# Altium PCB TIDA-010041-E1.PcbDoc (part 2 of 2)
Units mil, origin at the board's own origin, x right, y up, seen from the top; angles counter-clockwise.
Board outline 3937.01 x 2165.35 mil, 2 copper layers (Top Layer, Bottom Layer), stack 62 mil thick; 146 components, 79 nets, 325 pads, 93 vias.
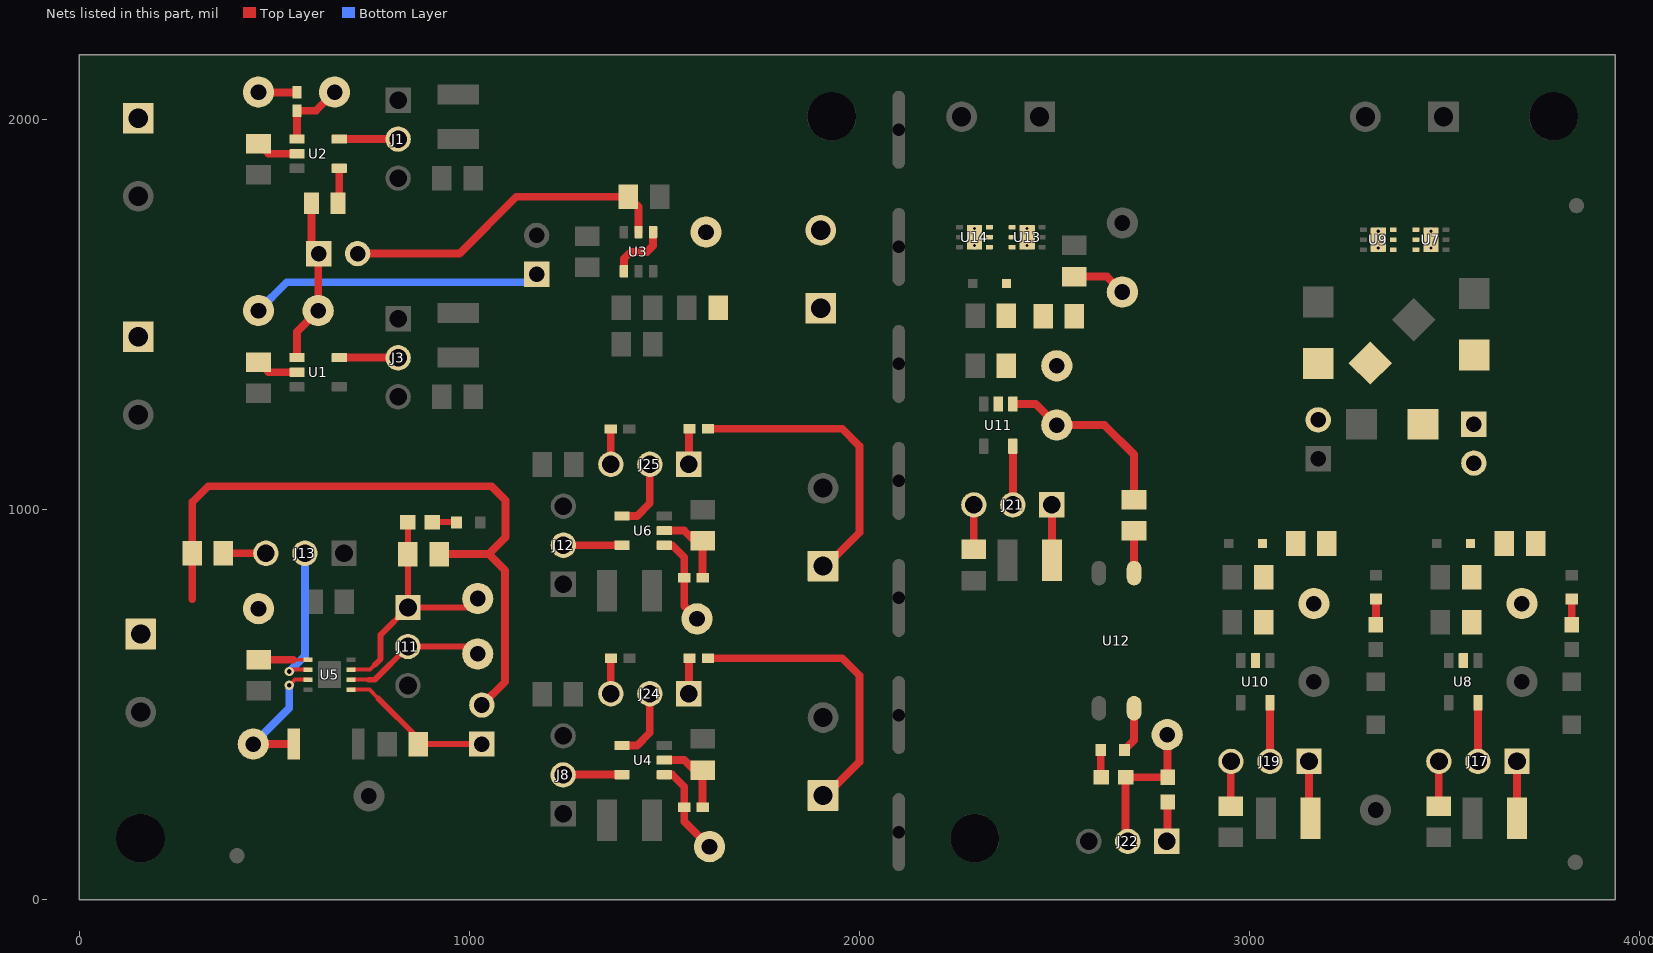
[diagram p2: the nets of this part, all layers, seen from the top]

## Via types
v1: diameter 24, hole 12, Top Layer to Bottom Layer, 81 vias
v2: diameter 19.68, hole 7.87, Top Layer to Bottom Layer, 12 vias

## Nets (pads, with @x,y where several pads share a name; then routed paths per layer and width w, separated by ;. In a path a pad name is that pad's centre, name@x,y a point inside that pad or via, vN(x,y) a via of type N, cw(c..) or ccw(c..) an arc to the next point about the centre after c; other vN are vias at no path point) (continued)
NetC17_1: C17.1 J17.1 | length 145.9
  Top Layer w20: J17.1@3685.4,354.6 3685.4,209.69 C17.1@3686.09,209
NetC18_2: C18.2 D5.1 R7.1 R9.2 TP16.1 U8.2
NetC19_1: C19.1 J17.3 | length 114.8
  Top Layer w20: C19.1@3485,240 3485,354.2 J17.3@3485.4,354.6
NetC20_1: C20.1 J19.1 | length 145.9
  Top Layer w20: J19.1@3152.4,354.6 3152.4,209.69 C20.1@3153.09,209
NetC21_2: C21.2 D8.1 R8.1 R10.2 TP17.1 U10.2
NetC22_1: C22.1 J19.3 | length 114.8
  Top Layer w20: C22.1@2952,240 2952,354.2 J19.3@2952.4,354.6
NetC23_1: C23.1 J21.1 | length 142
  Top Layer w20: C23.1@2493.4,870.1 J21.1@2493.4,1012.1
NetC24_2: C24.2 D10.1 R12.1 R14.2 TP20.1 U11.2
NetC25_1: C25.1 J21.3 | length 114.2
  Top Layer w20: C25.1@2293.4,897.9 J21.3@2293.4,1012.1
NetD2_1: D2.1 D3.1 J16.1
NetD6_2: D6.2 D7.2 J20.2
NetD9_1: D9.1 R17.1 | length 70.4
  Top Layer w20: D9.1@2618.49,384 2618.49,315.02 R17.1@2619.5,314
NetD9_2: D9.2 U12.4 | length 116.9
  Top Layer w20: D9.2@2679.51,384 2704.02,408.51 U12.4@2704.02,490.77
NetD11_1: D11.1 R25.2 | length 62.4
  Top Layer w15: R25.2@905.5,968 966.49,968 D11.1@967.49,967
NetD12_1: D12.1 R26.1 | length 66
  Top Layer w20: R26.1@3826,704.5 D12.1@3826,770.49
NetD13_1: D13.1 R27.1 | length 66
  Top Layer w20: R27.1@3324,704.5 D13.1@3324,770.49
NetJ1_2: J1.2 U2.5 | length 150.9
  Top Layer w20: U2.5@667.13,1949.4 J1.2@818,1949.4
NetJ2_2: J2.2 R2.2 U3.5 | length 855.9
  Top Layer w20: J2.2@714,1656 975,1656 1120.89,1801.89 R2.2@1407.89,1801.89 1433.89,1775.89 U3.5@1433.89,1711.09
NetJ3_2: J3.2 U1.5 | length 150.9
  Top Layer w20: U1.5@667.13,1389.4 J3.2@818,1389.4
NetJ7_1: J7.1 R3.2
NetJ8_2: J8.2 U4.5 | length 150.3
  Top Layer w20: J8.2@1241.49,320.6 U4.5@1391.76,320.6
NetJ11_1: J11.1 R5.2 R25.1 TP8.1 U5.7 | length 655.8
  Top Layer w10: U5.7@697.24,589.59 745.59,589.59 758.5,602.5
  Top Layer w15: 758.5,602.5 773,617 773,679 J11.1@843,749 ; R25.1@842.5,968 843,967.5 R5.2@843,886 J11.1@843,749 ; TP8.1@1022,772 999,749 J11.1@843,749
NetJ11_2: J11.2 TP9.1 U5.6 | length 367.8
  Top Layer w10: U5.6@697.24,564 742,564
  Top Layer w15: 742,564 758,564 J11.2@843,649 1003,649 TP9.1@1022,630
NetJ12_2: J12.2 U6.5 | length 150.3
  Top Layer w20: J12.2@1241.49,908.6 U6.5@1391.76,908.6
NetJ13_2: J13.2 U5.2 | length 369.5
  Top Layer w10: v1(539,585) 543.59,589.59 U5.2@587,589.59
  Bottom Layer w20: v1(539,585) 579,625 J13.2@579,888
NetJ13_3: J13.3 R6.2 | length 109
  Top Layer w20: R6.2@370,888 J13.3@479,888
NetJ15_1: J15.1 R15.1 U5.5 | length 401.2
  Top Layer w10: U5.5@697.24,538.41 744.59,538.41 767,516
  Top Layer w15: 767,516 870,413 R15.1@870,399 J15.1@1032.45,399
NetJ16_2: J16.2 R7.2 R8.2
NetJ17_2: J17.2 U8.5 | length 150.3
  Top Layer w20: J17.2@3585.4,354.6 U8.5@3585.4,504.87
NetJ19_2: J19.2 U10.5 | length 150.3
  Top Layer w20: J19.2@3052.4,354.6 U10.5@3052.4,504.87
NetJ21_2: J21.2 U11.5 | length 150.3
  Top Layer w20: J21.2@2393.4,1012.1 U11.5@2393.4,1162.37
NetJ24_1: J24.1 R20.1 | length 91.7
  Top Layer w20: J24.1@1563,528 1563,617.24 R20.1@1564.76,619
NetJ24_2: J24.2 U4.4 | length 184.7
  Top Layer w20: U4.4@1391.76,395.4 1430.33,395.4 1463,428.07 J24.2@1463,528
NetJ24_3: J24.3 R21.2 | length 91.2
  Top Layer w20: J24.3@1363,528 1363,618.62 R21.2@1363.38,619
NetJ25_1: J25.1 R23.1 | length 91.7
  Top Layer w20: J25.1@1563,1116 1563,1205.24 R23.1@1564.76,1207
NetJ25_2: J25.2 U6.4 | length 184.7
  Top Layer w20: U6.4@1391.76,983.4 1430.33,983.4 1463,1016.07 J25.2@1463,1116
NetJ25_3: J25.3 R24.2 | length 90.6
  Top Layer w20: J25.3@1363,1116 R24.2@1363,1206.62
NetR1_2: R1.2 U2.4 | length 91
  Top Layer w20: R1.2@663.65,1785 667.13,1788.49 U2.4@667.13,1874.6
NetR11_1: R11.1 TP18.1 U11.1 | length 479.8
  Top Layer w20: U11.1@2393.4,1270.63 2451.87,1270.63 TP18.1@2506,1216.5 2628.5,1216.5 2704,1141 R11.1@2704,1025.5
NetR11_2: R11.2 U12.1 | length 108.3
  Top Layer w20: U12.1@2704.02,837.23 R11.2@2704,945.5
NetR12_2: R12.2 R13.2 TP19.1 | length 139.4
  Top Layer w20: R13.2@2551,1597 2634.5,1597 TP19.1@2674,1557.5
NetS1_2: S1.2 TP12.1 U5.3 | length 341.7
  Top Layer w10: v1@543,553 554,564 U5.3@587,564
  Top Layer w20: TP12.1@446.51,399 S1.2@550.32,399
  Bottom Layer w20: TP12.1@446.51,399 539,491.49 v1(539,550)
NetU7_1: U7.1 U7.2 U7.3 U7.7@3465,1691.72 U9.1 U9.2 U9.3 U9.7@3330,1691.72 | length 86.6
  Bottom Layer w20: v2(3330,1670.06) v2(3330,1713.37) ; v2(3465,1670.06) v2(3465,1713.37)
NetU13_1: U13.1 U13.2 U13.3 U13.7@2430,1698.22 U14.1 U14.2 U14.3 U14.7@2295,1698.22 | length 86.6
  Bottom Layer w20: v2(2295,1676.56) v2(2295,1719.87) ; v2(2430,1676.56) v2(2430,1719.87)
OPA_out: J7.2 TP5.1 U3.1 U3.4 | length 155.8
  Top Layer w20: U3.1@1396.49,1610.69 1396.49,1642.86 1414.06,1660.43 1455.81,1660.43 1471.29,1675.92 U3.4@1471.29,1711.09
OPTO_OUT: J22.2 R16.1 R17.2 TP21.1 | length 384.4
  Top Layer w20: J22.2@2688,149.5 2682.5,155 R17.2@2682.5,314 2789.49,314 R16.1@2790,313.49 2790,422 TP21.1@2789,423
PS_IN1: C3.1 J4.1 J6.1 TP3.1 U1.2 | length 861
  Top Layer w20: C3.1@460,1378 486,1352 U1.2@558.87,1352
  Bottom Layer w20: TP3.1@460,1510 532.42,1582.42 1152.42,1582.42 J6.1@1172.89,1602.89
PS_IN2: C5.1 J5.1 R18.2 TP4.1 U2.2 | length 208.9
  Top Layer w20: C5.1@460,1938 486,1912 U2.2@558.87,1912 ; TP4.1@460,2069.83 460.59,2069.24 R18.2@559,2069.24
PS_OUT_1: J2.1 R1.1 TP1.1 U1.1 | length 426.1
  Top Layer w20: U1.1@558.87,1389.4 558.87,1455.7 TP1.1@613,1509.83 613,1655 J2.1@614,1656 595.54,1674.46 R1.1@595.54,1785
PS_OUT_2: R18.1 TP2.1 U2.1 | length 188.5
  Top Layer w20: U2.1@558.87,1949.4 558.87,2021.87 R18.1@559,2022 607,2022 TP2.1@655,2070
PS_RS1: C10.2 J10.1 R19.2 R20.2 U4.2 | length 962
  Top Layer w20: U4.2@1500.03,358 1551,358 1577,332 C10.2@1598.89,332 1598.24,331.35 1598.24,237.38 R19.2@1598.62,237 ; R20.2@1612,619 1956,619 2000,575 2000,353 1914,267 J10.1@1906.89,267
PS_RS2: C15.2 J14.1 R22.2 R23.2 U6.2 | length 960.6
  Top Layer w20: U6.2@1500.03,946 1551,946 1577,920 C15.2@1598.89,920 ; R22.2@1598.24,825.38 C15.2@1598.24,919.35 ; R23.2@1612,1207 1956,1207 2000,1163 2000,941 1914,855 J14.1@1906.89,855
RESET_1: R19.1 TP6.1 U4.1 | length 244.6
  Top Layer w20: U4.1@1500.03,320.6 1520.4,320.6 1551.38,289.62 R19.1@1551.38,237 1551.38,200.62 TP6.1@1616,136
RESET_2: R22.1 TP10.1 U6.1 | length 235.6
  Top Layer w20: U6.1@1500.03,908.6 1520.4,908.6 1551.38,877.62 R22.1@1551.38,825 1551,824.62 1551,753 TP10.1@1584,720
VCC_OPT: J22.1 R16.2 | length 101.8
  Top Layer w20: J22.1@2788,149.5 2790,151.5 R16.2@2790,250.5
VCC_WDT: C11.1 J9.1 J15.2 R5.1 R6.1 TP7.1 U5.1 | length 1921.8
  Top Layer w10: 549.18,615.18 U5.1@587,615.18
  Top Layer w20: 290,770 R6.1@290,888 290,1019 331,1060 1057,1060 1093,1024 1093,929 1050,886 ; C11.1@461,615 549,615 549.18,615.18 ; R5.1@923,886 1050,886 ; J15.2@1032.45,499 1092,558.55 1092,844 1050,886
pads on no net: FID1.1 FID2.1 FID3.1 H1.1 H2.1 H3.1 H4.1 H5.0 H6.0 H7.0 H8.0 LBL1.0 U1.4 U5.8 U7.7@3465,1674 U7.7@3465,1709.43 U8.4 U9.7@3330,1674 U9.7@3330,1709.43 U10.4 U11.4 U13.7@2430,1680.5 U13.7@2430,1715.93 U14.7@2295,1680.5 U14.7@2295,1715.93

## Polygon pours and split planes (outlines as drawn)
OPA_out on Top Layer "vdd" (solid, remove dead copper, pour order 86): 1567.73,1770.73 1538.28,1741.28 1466.47,1741.28 1457,1731.81 1457,1671.63 1468.19,1660.43 1944.41,1660.43 1956,1672.03 1956,1759 1944.27,1770.73
NetC8_1 on Top Layer "vdd" (solid, remove dead copper, pour order 84): 1458,1624 1463,1629 1500.03,1629 1504,1625.03 1504,1579 1511,1572 1577,1572 1583,1566 1583,1466.26 1577.93,1461.19 1529,1461.19 1524,1456.19 1524,1388 1520,1384 1446,1384 1443,1387 1443,1540 1458,1555
NetU7_1 on Top Layer "gn" (solid, pour order 78): 3315,1665.5 3315,1732.5 3327,1744.5 3461,1744.5 3477,1728.5 3477,1652.5 3467,1642.5 3328,1642.5 3315,1655.5
GND_GF on Top Layer "gn" (solid, pour order 72): 3519,794 3519,951 3511,959 3389,959 3382,952 3382,798 3387,793 3518,793 3519,794
GND_GF on Top Layer "gn" (solid, pour order 68): 2872,592 2872,984 3054,1166 3191,1166 3213,1166 3218,1161 3218,1095 3210,1087 3104,1087 2991,974 2986,969 2986,830 2986,591.72 2977.28,583 2881,583
NetC21_2 on Top Layer "gn" (solid, pour order 66): 3004,656 3006,658 3007,659 3007,695 3007,940 3013,946 3016,949 3131,949 3145,949 3149,945 3149,840 3155,834 3217,834 3224,827 3224,709 3215,700 3099,700 3070,671 3050,671 3032,653 3025,646 3025,591 3004,591
NetC18_2 on Top Layer "gn" (solid, pour order 64): 3537,656 3539,658 3540,659 3540,695 3540,940 3546,946 3549,949 3664,949 3678,949 3682,945 3682,840 3688,834 3750,834 3757,827 3757,709 3748,700 3632,700 3603,671 3583,671 3565,653 3558,646 3558,591 3537,591
NetJ16_2 on Top Layer "gn" (solid, pour order 62): 3707,883 3707,969 3696,980 3272,980 3247,955 3247,872 3243,868 3174,868 3167,875 3167,1030 3184,1047 3192,1055 3357,1055 3506,1055 3517,1066 3517,1144 3526,1153 3625,1153 3631,1147 3631,1061 3639,1053 3676,1053 3770,1053 3782,1041 3782,877 3774,869 3714,869 3707,876
I_TD_IN2 on Top Layer "gn" (solid, pour order 58): 3245,1271 3245,1086 3252,1079 3336,1079 3344,1087 3344,1166 3344,1268.5 3335,1277.5 3251.5,1277.5
NetD2_1 on Top Layer "gn" (solid, pour order 56): 3401,1183 3401,1309 3530,1438 3620,1438 3634,1424 3634,1200 3619,1185 3611,1177 3475,1177 3404,1177 3401,1180
NetD6_2 on Top Layer "gn" (solid, pour order 54): 3308,1436 3113,1436 3096,1419 3096,1201 3103,1194 3208,1194 3216,1202 3216,1296 3226,1306 3317,1306 3342,1331 3373,1362 3373,1371
I_TD_IN2 on Top Layer "gn" (solid, pour order 52): 3340,1810 3302,1772 3302,1506 3279,1483 3131,1483 3122,1492 3122,2053 3135,2066 3215,2066 3327,2066 3340,2053 3340,1810
I_TD_IN1 on Top Layer "gn" (solid, pour order 50): 3444,2054 3444,1803 3492,1755 3492,1627 3478,1613 3362,1497 3362,1487 3420,1429 3424,1429 3434,1429 3476,1471 3515,1510 3561,1510 3622,1510 3625,1513 3629,1517 3629,1663 3629,2058 3621,2066 3456,2066 3444,2054
NetU13_1 on Top Layer "gn" (solid, pour order 34): 2280,1672 2280,1739 2292,1751 2426,1751 2442,1735 2442,1659 2432,1649 2293,1649 2280,1662
GND_BV on Top Layer "gn" (solid, pour order 32): 2320,1246 2177,1246 2159,1264 2159,2045 2176,2062 2180,2066 2292,2066 2305,2053 2305,1810 2278,1783 2267,1772 2267,1702 2267,1639 2305,1601 2325,1581 2325,1517 2325,1337 2325,1251
NetC24_2 on Top Layer "gn" (solid, pour order 30): 2350,1476 2350,1335 2345,1330 2345,1246 2368,1246 2370,1248 2370,1299 2379,1308 2559,1308 2565,1314 2565,1422 2561,1426 2509,1426 2493,1442 2493,1607 2488,1612 2358,1612 2350,1604
NetR12_2 on Top Layer "gn" (solid, pour order 28): 2517,1587 2517,1459 2524,1452 2585,1452 2591,1458 2591,1589 2591,1620 2587,1624 2522,1624 2517,1619
BIN_V_IN on Top Layer "gn" (solid, pour order 26): 2457,1677 2457,1755 2409,1803 2409,2054 2421,2066 2558,2066 2586,2066 2594,2058 2594,1678 2594,1663 2588,1657 2583,1652 2481,1652 2464,1652 2457,1659
PS_RS1 on Top Layer "vo" (solid, pour order 20): 1558.89,298 1589,298 1669,218 1670,219 1917,219 1946,219 1953,226 1953,306 1947,312 1744,312 1705,312 1660,357 1654,363 1572,363 1569,363 1557,351 1557,300 1559,298
PS_RS2 on Top Layer "vo" (solid, pour order 18): 1558.89,886 1589,886 1669,806 1670,807 1917,807 1946,807 1953,814 1953,894 1947,900 1744,900 1705,900 1660,945 1654,951 1572,951 1569,951 1557,939 1557,888 1559,886
GND_WDT on Top Layer "vo" (solid, pour order 16): 566,804 566,689.33 610.62,644.71 610.62,553.62 604,547 510,547 495,562 134,562 121,562 116,557 113,554 113,532 113,407 123,397 314,397 375,458 388,471 603,471 610,464 610,213 617,206 800,206 807,206 813,212 818,217 818,393 818,425 745,498 704,498 681,498 673,506 671,508 671,604 671,665 642,694 627,709 627,759 627,809 624,812 569,812 566,809
VCC_WDT on Top Layer "vo" (solid, pour order 14): 497,588 134,588 114,608 114,794 131,811 495,811 520,786 520,673 520,598 510,588
NetJ7_1 on Top Layer "vo" (solid, pour order 8): 1629,1473 1949,1473 1953,1477 1953,1553 1947,1559 1619,1559 1615,1555 1615,1475 1617,1473
PS_IN1 on Top Layer "vo" (solid, pour order 6): 505,1342 421,1342 379,1384 114,1384 97,1401 97,1533 116,1552 118,1554 490,1554 498,1554 509,1543 509,1382 527,1364 580,1364 580,1342
GND_PS on Top Layer "vo" (solid, pour order 4): 427,1325 118,1325 101,1308 96,1303 96,1281 96,1175 107,1164 494,1164 498,1168 500,1170 500,1264 500,1318 493,1325
GND_PS on Top Layer "vo" (solid, pour order 2): 427,1885 118,1885 101,1868 96,1863 96,1841 96,1735 107,1724 494,1724 498,1728 500,1730 500,1824 500,1878 493,1885
PS_IN2 on Top Layer "vo" (solid, pour order 0): 505,1902 421,1902 379,1944 114,1944 97,1961 97,2093 116,2112 118,2114 490,2114 498,2114 509,2103 509,1942 527,1924 580,1924 580,1902
GND_RS on Top Layer "gn" (solid, pour order 80): 1482.35,385.14 1945.14,385.14 1951,391 1951,514 1938.76,526.24 1717.24,526.24 1653,462 1508,462 1481,435 1481,383 1482,382
GND_RS on Top Layer "gn" (solid, pour order 82): 1482.35,973.14 1945.14,973.14 1951,979 1951,1102 1938.76,1114.24 1717.24,1114.24 1653,1050 1508,1050 1481,1023 1481,971 1482,970
GND_GF on Bottom Layer "gn" (solid, pour order 76): 2872,2118 2884,2130 2901,2130 3886,2130 3899,2117 3899,89 3850,40 3845.3,35.3 2888.7,35.3 2872,52
I_TD_IN2 on Bottom Layer "gn" (solid, pour order 60): 3344,1087 3344,1545 3214,1675 3144,1675 3139,1670 3139,1608 3173,1574 3245,1502 3245,1271 3245,1086 3252,1079 3336,1079 3344,1087
GND_OPT on Bottom Layer "gn" (solid, pour order 42): 2839,539 2839,54 2820.3,35.3 2180.7,35.3 2159,57 2159,542 2171,554 2645,554 2824,554
GND_BV on Bottom Layer "gn" (solid, pour order 40): 2159,2045 2159,789 2182,766 2824,766 2838,780 2838,2112 2820,2130 2173,2130 2159,2116
GND_WDT on Bottom Layer "gn" (solid, pour order 24): 1123,1118 58,1118 47,1107 37,1097 37,1062 37,88 75,50 89.7,35.3 1106.3,35.3 1127,56 1127,1114
GND_RS on Bottom Layer "vo" (solid, pour order 22): 2013,1328 1301,1328 1149,1176 1149,57 1171,35 2023,35 2041,53 2041,1300
GND_PS on Bottom Layer "vo" (solid, pour order 12): 494,1164 1108,1164 1218,1274 1307,1363 2008,1363 2041,1396 2041,1430 2041,2097 2008,2130 65,2130 37,2102 37,1178 51,1164

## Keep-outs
Keep-Out Layer:
  the board outline again, w10
  text ".Layer_Name" at 216.39,-1758.67 h60

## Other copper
Top Layer:
  text ".Layer_Name" at 216.39,-1758.67 h60
Bottom Layer:
  text ".Layer_Name" at 216.39,-1758.67 h60

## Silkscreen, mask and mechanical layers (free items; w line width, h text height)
Top Overlay:
  lines w20: 2101,0 2101,173.42 2101,2164
  text "'.PRJ_Number'" at 1079,2044 h60
  text "'.PCB_Rev'" at 1714,2042 h60
  text ".Layer_Name" at 216.39,-1758.67 h60
Bottom Overlay:
  text ".Layer_Name" at 216.39,-1758.67 h60
Top Paste:
  text ".Layer_Name" at 216.39,-1758.67 h60
Bottom Paste:
  text ".Layer_Name" at 216.39,-1758.67 h60
Top Solder:
  text ".Layer_Name" at 216.39,-1758.67 h60
  text ".Layer_Name" at 216.39,-1758.67 h60
Bottom Solder:
  text ".Layer_Name" at 216.39,-1758.67 h60
Drill Guide:
  text ".Layer_Name" at 216.39,-1758.67 h60
M1 Board Outline:
  the board outline again, w10
M2 Board Dimensions:
  rectangle: -360.61,-1175.18 -235.61,-1050.18
  rectangle: -235.61,-1300.18 139.39,-1175.18
  lines w7: -360.61,-1175.18 639.39,-1175.18 ; -235.61,-1300.18 -235.61,-1050.18 ; -110.61,-1300.18 -110.61,-1050.18 ; 139.39,-1300.18 139.39,-1050.18 ; 389.39,-1300.18 389.39,-1050.18 ; -360.61,-1300.18 639.39,-1300.18 639.39,-1050.18 -360.61,-1050.18 -360.61,-1300.18
M3 3D STEP Top:
  text ".Layer_Name" at 216.39,-1758.67 h60
M4 3D STEP Bottom:
  text ".Layer_Name" at 216.39,-1758.67 h60
M5 Assembly Top:
  circle w10: c3684,357 r14.76
  circle w10: c3151,353 r14.76
  circle w10: c3053,633 r7.28
  circle w10: c3576,1215 r14.76
  circle w10: c3178,1129 r14.76
  circle w10: c3499,2008 r14.76
  circle w10: c2788,148 r14.76
  circle w10: c2495,1015 r14.76
  circle w10: c2393,1288 r6.08
  circle w10: c2457,2004 r14.76
  circle w10: c154,678 r14.76
  circle w10: c680,893 r14.76
  circle w10: c841,749 r14.76
  circle w10: c1032,404 r14.76
  circle w10: c1465,321 r4.12
  circle w10: c1243,221 r14.76
  circle w10: c1911,270 r14.76
  circle w10: c1242,810 r14.76
  circle w10: c1464,910 r4
  circle w10: c1910,857 r14.76
  circle w10: c1903,1514 r14.76
  circle w10: c1172,1603 r14.76
  circle w10: c816,1492 r14.76
  circle w10: c594,1392 r3.16
  circle w10: c150,1440 r14.76
  circle w10: c614,1654 r14.76
  circle w10: c816,2048 r14.76
  circle w10: c544,1950 r5.1
  circle w10: c152,2003 r24.35
  circle w10: c3585,636 r9.06
  circle w10: c1565,522 r14.76
  circle w10: c1565,1114 r14.76
  lines w10: -652.61,-1830.35 5947.39,-1830.35 ; -652.61,-1627.01 5949.39,-1627.01 ; -652.61,-1423.68 -652.61,-2033.68 3352.39,-2033.68 5949.39,-2033.68 5949.39,-1423.68 -652.11,-1423.68 -652.11,-2033.68 923.39,-2033.68 ; 1812.39,-2033.68 1812.39,-1423.68 ; 3079.39,-1627.01 3079.39,-1423.68 ; 3919.39,-1627.01 3919.39,-1423.68 ; 4541.39,-2040.18 4541.39,-1837.35
  text "COMPONENTS MARKED 'DNP' SHOULD NOT BE POPULATED." at 792.89,-1218.68 h25
  text "ASSEMBLY VARIANT:" at 792.39,-1334.18 h25
  text ".VariantName" at 1828.39,-1334.18 h25
  text "PCB VIEWED FROM TOP SIDE" at -589.11,-1555.85 h25
  text "BOARD #:" at 1887.39,-1555.85 h25
  text "REV:" at 3277.39,-1555.85 h25
  text ".PCB_Rev" at 3568.89,-1555.85 h25
  text "SVN REV:" at 4115.39,-1555.85 h25
  text ".VersionControl_RevNumber" at 4621.39,-1555.85 h25
  text ".PRJ_Number" at 2191,-1563.6 h25
  text "'.Layer_Name'" at 182,-1756.6 h25
  text "TID #:" at 1887.39,-1759.18 h25
  text ".TID" at 2432.89,-1759.18 h25
  text "LAYER NAME =" at -583.11,-1761.67 h25
  text "PLOT NAME =" at -589.11,-1964.52 h25
  text ".plot_File_Name" at 216.39,-1964.52 h25
  text "GENERATED    :" at 1889.39,-1964.52 h25
  text ".Print_Date" at 2758.89,-1964.52 h25
  text ".Print_Time" at 3487.89,-1964.52 h25
  text "TEXAS INSTRUMENTS" at 4752.39,-1964.52 h25
M6 Assembly Bottom:
  lines w10: -653.11,-1627.51 5948.89,-1627.51 ; -651.11,-1830.85 5948.89,-1830.85 ; 754.89,-2040.68 754.89,-1837.85 ; 1376.89,-1627.51 1376.89,-1424.18 ; 2216.89,-1627.51 2216.89,-1424.18 ; 3483.89,-2034.18 3483.89,-1424.18 ; 4372.89,-2034.18 5948.39,-2034.18 5948.39,-1424.18 -653.11,-1424.18 -653.11,-2034.18 1943.89,-2034.18 5948.89,-2034.18 5948.89,-1424.18
  text "COMPONENTS MARKED 'DNP' SHOULD NOT BE POPULATED." at 5741.39,-1218.18 h25
  text ".VariantName" at 4697.39,-1334.18 h25
  text "ASSEMBLY VARIANT:" at 5736.39,-1334.18 h25
  text ".VersionControl_RevNumber" at 674.89,-1556.35 h25
  text "SVN REV:" at 1180.89,-1556.35 h25
  text ".PCB_Rev" at 1727.39,-1556.35 h25
  text "REV:" at 2018.89,-1556.35 h25
  text ".PRJ_Number" at 2863.39,-1556.35 h25
  text "BOARD #:" at 3408.89,-1556.35 h25
  text "PCB VIEWED FROM BOTTOM SIDE" at 5885.39,-1556.35 h25
  text "'.Layer_Name'" at 4992,-1749.6 h25
  text ".TID" at 2863.39,-1759.68 h25
  text "TID #:" at 3408.89,-1759.68 h25
  text "LAYER NAME =" at 5851,-1760.6 h25
  text "TEXAS INSTRUMENTS" at 543.89,-1965.02 h25
  text ".Print_Time" at 1808.39,-1965.02 h25
  text ".Print_Date" at 2537.39,-1965.02 h25
  text "GENERATED    :" at 3406.89,-1965.02 h25
  text ".plot_File_Name" at 5079.89,-1965.02 h25
  text "PLOT NAME =" at 5885.39,-1965.02 h25
M9 Title Sheet:
  drawing of 57 lines, arcs and shapes, not listed
  text "1" at 379.22,7136.32 h70
  text "2" at 2874.89,7136.32 h70
  text "3" at 5364.23,7136.32 h70
  text "4" at 7870.9,7136.32 h70
  text "5" at 10369.89,7136.32 h70
  text "6" at 12874.89,7136.32 h70
  text "A" at -777.11,5993.32 h70
  text "A" at 14022.89,5993.32 h70
  text "A" at 14024.91,5992.54 h70
  text "B" at -777.11,3613.32 h70
  text "B" at 14022.89,3613.32 h70
  text "B" at 14024.91,3612.54 h70
  text "C" at -777.11,1238.32 h70
  text "C" at 14022.89,1238.32 h70
  text "C" at 14024.91,1237.54 h70
  text "PROJECT TITLE:" at 10982.89,-622.68 h45
  text ".PRJ_Title" at 11032.89,-756.01 h70
  text "DESIGNED FOR:" at 10982.89,-923.68 h45
  text ".PRJ_Customer" at 11032.89,-1063.68 h70
  text "D" at -777.11,-1131.68 h70
  text "D" at 14022.89,-1131.68 h70
  text "FILE NAME:" at 10982.89,-1223.68 h45
  text ".PCB_File_Name_No_Path" at 11032.89,-1343.68 h70
  text "Texas Instruments (TI) and/or its licensors do not warrant the accuracy or completeness of this specification" at 6013.39,-1505.52 h45
  text "ENGINEER:" at 10982.89,-1513.68 h45
  text "LAYOUT BY:" at 12487.89,-1513.68 h45
  text "or any information contained therein. TI and/or its licensors do not warrant that this design will meet" at 5968.4,-1618.18 h45
  text ".PRJ_Engineer" at 11032.89,-1668.67 h70
  text ".PCB_Layout" at 12538.39,-1668.67 h70
  text "the specifications, will be suitable for your application or fit for any particular purpose, or will operate in" at 5968.4,-1730.85 h45
  text "ALTIUM DESIGNER VERSION:" at 12487.89,-1823.68 h45
  text "an implementation. TI and/or its licensors do not warrant that the design is production worthy. You should" at 5968.4,-1843.52 h45
  text "completely validate and test your design implementation to confirm the system functionality for your application." at 6013.39,-1956.18 h45
  text ".print_Scale" at 11032.89,-1957.01 h70
  text ".Application_BuildNumber" at 12538.39,-1957.01 h70
  text "1" at 379.22,-2163.68 h70
  text "2" at 2874.89,-2163.68 h70
  text "3" at 5364.23,-2163.68 h70
  text "4" at 7870.9,-2163.68 h70
  text "5" at 10369.89,-2163.68 h70
  text "6" at 12874.89,-2163.68 h70
M10 Fab Notes:
  drawing of 227 lines, arcs and shapes, not listed
  text "DESIGN INFORMATION" at 12010.86,5899.76 h60
  text "(REFER ALSO ARRAY/PANEL PROFILING INFORMATION)" at 11659.35,5733.69 h60
  text "BOARD SIZE" at 10973.35,5729.4 h60
  text "55MM" at 12232,5605.4 h60
  text "100MM" at 11453,5602.4 h60
  text "X" at 11941.35,5601.58 h60
  text "Number of Layers :" at 11376.34,5404.4 h60
  text "2" at 12448.89,5399.4 h60
  text "10" at 12449.82,5267.61 h60
  text "MIN. TRACK WIDTH:" at 11376.34,5265.4 h60
  text "MIL" at 12627.34,5265.4 h60
  text "7.874" at 12324,5139.4 h60
  text "MIN. CLEARANCE:" at 11376.34,5133.4 h60
  text "MIL" at 12627.34,5133.4 h60
  text "MIN. VIA DRILL SIZE:" at 11376.34,5001.4 h60
  text "7.874" at 12314.82,5001.61 h60
  text "MIL" at 12627.34,5001.4 h60
  text "5.90 MIL" at 12071.35,4859.69 h60
  text "MINIMUM ANNULAR RING" at 11047.11,4855.41 h60
  text "EXTERNAL" at 12962.89,4844.4 h60
  text "PER" at 11247.11,4737.41 h60
  text "IPC-D-275 CLASS 2 LEVEL C" at 11467.11,4737.4 h60
  text "+/-" at 12562.89,4624.4 h60
  text "MIL, HOLES" at 12955.34,4625.11 h60
  text "+/-" at 13416.89,4624.4 h60
  text "REGISTRATION TOLERANCES:" at 11047.11,4619.4 h60
  text "METAL" at 12246.89,4619.4 h60
  text "5" at 12823.09,4619.41 h60
  text "3" at 13656.09,4619.41 h60
  text "MIL" at 13772.34,4619.4 h60
  text "MATERIAL:" at 10972.35,4409.94 h60
  text "FR-4 High Tg" at 11958.79,4269.61 h60
  text "X" at 11799.89,4261.4 h60
  text "FR-408" at 11393.35,4261.04 h60
  text "OTHER" at 12881.35,4261.04 h60
  text "63 MIL (1.6mm) +/-10%" at 11713.45,4098.32 h60
  text "THICKNESS:" at 11047.11,4094.04 h60
  text "X" at 11585.28,4094.04 h60
  text "OTHER" at 12998.35,4094.04 h60
  text "TOLERANCE:" at 11047.11,3936.04 h60
  text "X" at 11886.42,3936.04 h60
  text "ANSI IPC-6012 TYPE 3 CLASS 2" at 12073.36,3936.04 h60
  text "OTHER +/-" at 12073.35,3780.04 h60
  text "BOW & TWIST:" at 11047.11,3623.04 h60
  text "X" at 11886.42,3623.04 h60
  text "ANSI IPC-6012 TYPE 3 CLASS 2" at 12073.36,3623.04 h60
  text "OTHER +/-" at 12073.35,3464.53 h60
  text "COPPER THICKNESS (FINISHED):" at 10972.35,3329.04 h60
  text "1.4MIL (1oz)" at 11852.34,3176.32 h60
  text "2MIL (1.4oz)" at 12619.35,3176.32 h60
  text "2.8MIL (2oz)" at 13346.35,3176.32 h60
  text "OUTER:" at 11329.35,3172.04 h60
  text "X" at 11723.89,3171.4 h60
  text "1.4MIL (1oz)" at 11852.34,3019.32 h60
  text "2.8MIL (2oz)" at 12619.35,3019.32 h60
  text "N/A" at 13345.89,3019.69 h60
  text "INNER SIGNAL:" at 11040.26,3015.04 h60
  text "X" at 13216.37,3008.04 h60
  text "DRILLING:" at 10972.35,2876.04 h60
  text "REFERENCE:" at 11047.11,2759.04 h60
  text "X" at 11695.35,2759.04 h60
  text "AS SHOWN" at 11882.34,2759.04 h60
  text "X" at 12596.35,2759.04 h60
  text "NC_DRILL FILES" at 12733.34,2759.04 h60
  text "PTH MIN COPPER THICKNESS:" at 11047.11,2601.04 h60
  text "X" at 12397.35,2601.04 h60
  text "1MIL" at 12534.34,2601.04 h60
  text "OTHER" at 13031.35,2601.04 h60
  text "BOARD FINISH:" at 10972.35,2442.04 h60
  text "SILKSCREEN:" at 11127.57,2324.04 h60
  text "X" at 12076.35,2324.04 h60
  text "TOP" at 12202.34,2324.04 h60
  text "X" at 12586.35,2324.04 h60
  text "BOTTOM" at 12713.34,2324.04 h60
  text "SILKSCREEN COLOR:" at 11127.57,2157.04 h60
  text "X" at 12075.3,2157.04 h60
  text "WHITE" at 12202.34,2157.04 h60
  text "OTHER" at 12713.34,2157.04 h60
  text "SOLDER RESIST COLOR:" at 11127.57,1987.04 h60
  text "X" at 11695.31,1827.84 h60
  text "GREEN" at 11822.34,1827.84 h60
  text "BLUE" at 12413.34,1827.84 h60
  text "OTHER" at 12951.35,1827.84 h60
  text "IMMERSION GOLD (ENIG)" at 12033.34,1639.32 h60
  text "ENEPIG" at 13370.89,1636.04 h60
  text "SURFACE FINISH:" at 10972.35,1635.04 h60
  text "X" at 11846.4,1635.04 h60
  text "IMM. TIN/SILVER OR EQUIV" at 11301.89,1478.04 h60
  text "OTHER" at 12733.35,1478.04 h60
  text "ARRAY/PANEL:" at 10972.35,1299.04 h60
  text "CUT AND TRIM PER MECH LAYER 1" at 12033.35,1294.76 h60
  text "N.C. ROUTE" at 12033.34,1143.04 h60
  text "X" at 12712.35,1143.04 h60
  text "V. SCORE" at 12899.35,1143.04 h60
  text "CERTIFICATION:" at 10972.35,1006.04 h60
  text "MATERIALS AND WORKMANSHIP FOR ALL PCBS" at 11697.35,1006.04 h60
  text "TO MEET OR EXCEED THE REQUIREMENTS OF:" at 11697.35,908.04 h60
  text "X" at 11323.85,771.54 h60
  text "ANSI IPC-A-600F CLASS ->" at 11462.85,771.54 h60
  text "X" at 13101.9,771.54 h60
  text "2" at 13220.85,771.54 h60
  text "1" at 12905.85,770.04 h60
  text "3" at 13574.85,770.04 h60
  text "X" at 11325.9,612.04 h60
  text "UL 94V-0" at 11462.85,612.04 h60
  text "X" at 12137.9,612.04 h60
  text "RoHS" at 12274.85,612.04 h60
  text "OTHER" at 12919.25,612.04 h60
  text "PER ORDER" at 13316.31,612.04 h60
  text "X" at 13266,482.4 h60
  text "VIA TENTING:" at 12189.89,478.4 h60
  text "ADDITIONAL REQUIREMENTS:" at 10972.35,471.04 h60
  text "YES" at 12739.55,469.32 h60
  text "NO" at 13104.36,464.09 h60
  text "MICROSECTION:" at 11047.11,356.04 h60
  text "YES" at 11952.85,356.04 h60
  text "IMPEDANCE CONTROL:" at 12211.89,349.4 h60
  text "YES" at 13195.89,348.4 h60
  text "X" at 13737.89,341.4 h60
  text "NO" at 13571.36,331.09 h60
  text "REQUIRED" at 12814.34,199.9 h60
  text "BARE BOARD ELEC. TEST:" at 11047.11,197.04 h60
  text "NONE" at 12352.85,197.04 h60
  text "X" at 12687.35,197.04 h60
  text "PER ORDER" at 13406.35,197.04 h60
  text "MANUFACTURER'S UL:" at 11047.11,40.04 h60
  text "RAIL" at 12212.85,35.76 h60
  text "METAL" at 12704.66,35.76 h60
  text "X" at 13079.89,35.4 h60
  text "SILK" at 13216.34,35.76 h60
M11 Gerber Information:
  lines w10: -652.61,-1830.35 5947.39,-1830.35 ; -652.61,-1627.01 5949.39,-1627.01 ; -652.61,-1423.68 -652.61,-2033.68 3352.39,-2033.68 5949.39,-2033.68 5949.39,-1423.68 -652.11,-1423.68 -652.11,-2033.68 923.39,-2033.68 ; 1812.39,-2033.68 1812.39,-1423.68 ; 3079.39,-1627.01 3079.39,-1423.68 ; 3919.39,-1627.01 3919.39,-1423.68 ; 4541.39,-2040.18 4541.39,-1837.35
  text "ALL ARTWORK VIEWED FROM TOP SIDE" at -589.11,-1555.85 h60
  text "BOARD #:" at 1887.39,-1555.85 h60
  text ".PRJ_Number" at 2432.89,-1555.85 h60
  text "REV:" at 3277.39,-1555.85 h60
  text ".PCB_Rev" at 3568.89,-1555.85 h60
  text "SVN REV:" at 4115.39,-1555.85 h60
  text ".VersionControl_RevNumber" at 4621.39,-1555.85 h60
  text "LAYER NAME =" at -589.11,-1758.67 h60
  text "TID #:" at 1887.39,-1759.18 h60
  text ".TID" at 2432.89,-1759.18 h60
  text "PLOT NAME =" at -589.11,-1964.52 h60
  text ".plot_File_Name" at 216.39,-1964.52 h60
  text "GENERATED    :" at 1889.39,-1964.52 h60
  text ".Print_Date" at 2758.89,-1964.52 h60
  text ".Print_Time" at 3487.89,-1964.52 h60
  text "TEXAS INSTRUMENTS" at 4752.39,-1964.52 h60
M12 Stackup:
  drawing of 191 lines, arcs and shapes, not listed
  text "Layer" at 5058.58,3224 h60
  text "Name" at 5468.49,3224 h60
  text "Material" at 6398.23,3224 h60
  text "Thickness" at 7258,3224 h60
  text "Constant" at 7907.84,3224 h60
  text "Board Layer Stack" at 8477.7,3224 h60
  text "1" at 5058.58,3104 h60
  text "Top Overlay" at 5468.49,3104 h60
  text "2" at 5058.58,2984 h60
  text "Top Solder" at 5468.49,2984 h60
  text "Solder Resist" at 6398.23,2984 h60
  text "0.40mil" at 7258,2984 h60
  text "3.5" at 7907.84,2984 h60
  text "3" at 5058.58,2864 h60
  text "Top Layer" at 5468.49,2864 h60
  text "Copper" at 6398.23,2864 h60
  text "1.40mil" at 7258,2864 h60
  text "4" at 5058.58,2744 h60
  text "Dielectric1" at 5468.49,2744 h60
  text "FR-4 High Tg" at 6398.23,2744 h60
  text "59.20mil" at 7258,2744 h60
  text "4.8" at 7907.84,2744 h60
  text "5" at 5058.58,2624 h60
  text "Bottom Layer" at 5468.49,2624 h60
  text "Copper" at 6398.23,2624 h60
  text "1.40mil" at 7258,2624 h60
  text "6" at 5058.58,2504 h60
  text "Bottom Solder" at 5468.49,2504 h60
  text "Solder Resist" at 6398.23,2504 h60
  text "0.40mil" at 7258,2504 h60
  text "3.5" at 7907.84,2504 h60
  text "7" at 5058.58,2384 h60
  text "Bottom Overlay" at 5468.49,2384 h60
M13 Component Bodies Top:
  text ".Layer_Name" at 216.39,-1758.67 h60
M14 Component Bodies Bottom:
  text ".Layer_Name" at 216.39,-1758.67 h60
M15 Courtyards Top:
  text ".Layer_Name" at 216.39,-1758.67 h60
M16 Courtyards Bottom:
  text ".Layer_Name" at 216.39,-1758.67 h60
Drill Drawing:
  circle w10: c4218.62,5930.68 r33.33
  lines w10: 4185.29,5464.01 4201.96,5464.01 4218.62,5447.34 4235.29,5464.01 4251.96,5464.01 4235.29,5480.68 4251.96,5497.34 4235.29,5497.34 4218.62,5514.01 4201.96,5497.34 4185.29,5497.34 4201.96,5480.68 4185.29,5464.01 ; 4185.29,5614.01 4201.96,5614.01 4201.96,5597.34 4235.29,5597.34 4235.29,5614.01 4251.96,5614.01 4251.96,5647.34 4235.29,5647.34 4235.29,5664.01 4201.96,5664.01 4201.96,5647.34 4185.29,5647.34 4185.29,5614.01 ; 4185.29,5780.68 4218.62,5747.34 4251.96,5780.68 4218.62,5814.01 4185.29,5780.68 ; 4185.29,6047.34 4251.96,6047.34 4251.96,6114.01 4185.29,6114.01 4185.29,6047.34 ; 4185.29,6264.01 4251.96,6264.01 4218.62,6197.34 4185.29,6264.01
  lines w15: 4125.5,5252.34 7690.56,5252.34 ; 4125.5,6302.34 7690.56,6302.34 ; 4676.38,5102.34 4676.38,6452.34 ; 5266.22,5102.34 5266.22,6452.34 ; 6405.89,5102.34 6405.89,6452.34 ; 6911.76,5102.34 6911.76,6452.34 ; 4125.5,5102.34 7690.56,5102.34 7690.56,6452.34 4125.5,6452.34 4125.5,5102.34
  text "Symbol" at 4215.5,6347.34 h72
  text "Count" at 4721.38,6347.34 h72
  text "Hole Size" at 5311.22,6347.34 h72
  text "Plated" at 6450.89,6347.34 h72
  text "Hole Type" at 6956.76,6347.34 h72
  text "12" at 4721.38,6197.34 h60
  text "7.87mil (0.200mm)" at 5311.22,6197.34 h60
  text "PTH" at 6450.89,6197.34 h60
  text "Round" at 6956.76,6197.34 h60
  text "81" at 4721.38,6047.34 h60
  text "12.00mil (0.305mm)" at 5311.22,6047.34 h60
  text "PTH" at 6450.89,6047.34 h60
  text "Round" at 6956.76,6047.34 h60
  text "7" at 4721.38,5897.34 h60
  text "32.00mil (0.813mm)" at 5311.22,5897.34 h60
  text "NPTH" at 6450.89,5897.34 h60
  text "Slot" at 6956.76,5897.34 h60
  text "32" at 4721.38,5747.34 h60
  text "40.00mil (1.016mm)" at 5311.22,5747.34 h60
  text "PTH" at 6450.89,5747.34 h60
  text "Round" at 6956.76,5747.34 h60
  text "36" at 4721.38,5597.34 h60
  text "45.28mil (1.150mm)" at 5311.22,5597.34 h60
  text "PTH" at 6450.89,5597.34 h60
  text "Round" at 6956.76,5597.34 h60
  text "16" at 4721.38,5447.34 h60
  text "49.21mil (1.250mm)" at 5311.22,5447.34 h60
  text "PTH" at 6450.89,5447.34 h60
  text "Round" at 6956.76,5447.34 h60
  text "4" at 4721.38,5297.34 h60
  text "125.00mil (3.175mm)" at 5311.22,5297.34 h60
  text "NPTH" at 6450.89,5297.34 h60
  text "Round" at 6956.76,5297.34 h60
  text "D" at 4186.41,5287.35 h66.67
  text "188 Total" at 4721.38,5147.34 h60
  text "Slot definitions :" at 4215.5,5002.37 h60
  text "Routed Path Length" at 5248.19,5002.37 h60
  text "= Calculated from tool start centre position to tool end centre position." at 6350.86,5002.37 h60
  text "Hole Length" at 5248.19,4902.4 h60
  text "= Routed Path Length + Tool Size = Slot length as defined in the PCB layout" at 5940.99,4902.4 h60
  text "Drill Table" at 4081.77,4731.4 h60
  text "FOR 7.874MIL DRILL +0/-7.874MIL" at 4082,4595.4 h60
  text "FOR 12MIL DRILL +0/-12MIL" at 4082,4496.4 h60
  text "FOR 16MIL DRILL +0/-16MIL" at 4081.77,4407.4 h60
  text "FOR PTH DRILL +/-3MIL" at 4077.51,4320.85 h60
  text "FOR NPTH DRILL +/-2MIL" at 4081.77,4237.4 h60
  text ".Layer_Name" at 216.39,-1758.67 h60
Mechanical 17:
  text ".Layer_Name" at 216.39,-1758.67 h60
Mechanical 18:
  text ".Layer_Name" at 216.39,-1758.67 h60
Mechanical 19:
  text ".Layer_Name" at 216.39,-1758.67 h60

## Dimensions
3937.01,0 to 0,0 on M2 Board Dimensions
0,0 to 0,2165.35 on M2 Board Dimensions
-360.61,-1300.18 to 639.39,-1300.18 on M2 Board Dimensions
